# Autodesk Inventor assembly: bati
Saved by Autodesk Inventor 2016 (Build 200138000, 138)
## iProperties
Created: 2013-10
Part Number: bati
Material: Générique
Document SubType Name: Assembly
Designer: Bruno
Author: Bruno
Sending System: SolidWorks 2013
Last Author: christophe
Last Saved: 2014-02-15
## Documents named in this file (16)
- D:\Cours\Systèmes SI\Robot Haptique\Documentations_pedagogique\Modèle solidworks\Réel\bati.iam
- D:\Cours\Systèmes SI\Robot Haptique\Documentations_pedagogique\Modèle solidworks\Réel\MOTEUR.ipt
- D:\Cours\Systèmes SI\Robot Haptique\Documentations_pedagogique\Modèle solidworks\Réel\FIXATION MOTEUR.ipt
- D:\Cours\Systèmes SI\Robot Haptique\Documentations_pedagogique\Modèle solidworks\Réel\Vis à tôle tête cylindrique cruciforme H 2,9x13 - C.ipt
- D:\Cours\Systèmes SI\Robot Haptique\Documentations_pedagogique\Modèle solidworks\Réel\socle.ipt
- D:\Cours\Systèmes SI\Robot Haptique\Documentations_pedagogique\Modèle solidworks\Réel\vis CHC M4-30.ipt
- D:\Cours\Systèmes SI\Robot Haptique\Documentations_pedagogique\Modèle solidworks\Réel\Rondelle M4.ipt
- D:\Cours\Systèmes SI\Robot Haptique\Documentations_pedagogique\Modèle solidworks\Réel\CARTE HEXAGONALE.ipt
- D:\Cours\Systèmes SI\Robot Haptique\Documentations_pedagogique\Modèle solidworks\Réel\petite carte.ipt
- D:\Cours\Systèmes SI\Robot Haptique\Documentations_pedagogique\Modèle solidworks\Réel\Vis à tôle tête cylindrique cruciforme H 2,9x8 - C.ipt
- D:\Cours\Systèmes SI\Robot Haptique\Documentations_pedagogique\Modèle solidworks\Réel\plaque fixation.ipt
- D:\Cours\Systèmes SI\Robot Haptique\Documentations_pedagogique\Modèle solidworks\Réel\CARTER ARRIERE.ipt
- D:\Cours\Systèmes SI\Robot Haptique\Documentations_pedagogique\Modèle solidworks\Réel\carter transparant.iam
- D:\Cours\Systèmes SI\Robot Haptique\Documentations_pedagogique\Modèle solidworks\Réel\carter avant.iam
- D:\Cours\Systèmes SI\Robot Haptique\Documentations_pedagogique\Modèle solidworks\Réel\PLAQUE NOM.ipt
- D:\Cours\Systèmes SI\Robot Haptique\Documentations_pedagogique\Modèle solidworks\Réel\CACHE.ipt
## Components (51 placed, 15 different names)
1. MOTEUR:1
2. FIXATION MOTEUR:1
3. FIXATION MOTEUR:2
4. Vis à tôle tête cylindrique cruciforme H 2,9x13 - C:1
5. Vis à tôle tête cylindrique cruciforme H 2,9x13 - C:2
6. Vis à tôle tête cylindrique cruciforme H 2,9x13 - C:3
7. Vis à tôle tête cylindrique cruciforme H 2,9x13 - C:4
8. socle:1
9. vis CHC M4-30:1
10. vis CHC M4-30:2
11. Rondelle M4:1
12. Rondelle M4:2
13. CARTE HEXAGONALE:1
14. Vis à tôle tête cylindrique cruciforme H 2,9x13 - C:5
15. petite carte:1
16. Vis à tôle tête cylindrique cruciforme H 2,9x8 - C:1
17. Vis à tôle tête cylindrique cruciforme H 2,9x13 - C:7
18. Vis à tôle tête cylindrique cruciforme H 2,9x8 - C:2
19. Vis à tôle tête cylindrique cruciforme H 2,9x8 - C:3
20. petite carte:2
21. petite carte:3
22. Vis à tôle tête cylindrique cruciforme H 2,9x13 - C:8
23. Vis à tôle tête cylindrique cruciforme H 2,9x13 - C:9
24. Vis à tôle tête cylindrique cruciforme H 2,9x13 - C:10
25. Vis à tôle tête cylindrique cruciforme H 2,9x13 - C:11
26. Vis à tôle tête cylindrique cruciforme H 2,9x13 - C:12
27. Vis à tôle tête cylindrique cruciforme H 2,9x13 - C:13
28. Vis à tôle tête cylindrique cruciforme H 2,9x13 - C:14
29. Vis à tôle tête cylindrique cruciforme H 2,9x13 - C:15
30. MOTEUR:2
31. MOTEUR:3
32. FIXATION MOTEUR:3
33. FIXATION MOTEUR:4
34. Vis à tôle tête cylindrique cruciforme H 2,9x13 - C:16
35. Vis à tôle tête cylindrique cruciforme H 2,9x13 - C:17
36. plaque fixation:1
37. CARTER ARRIERE:1
38. carter transparant:5 [sub-assembly]
39. Vis à tôle tête cylindrique cruciforme H 2,9x13 - C:18
40. Vis à tôle tête cylindrique cruciforme H 2,9x13 - C:19
41. Vis à tôle tête cylindrique cruciforme H 2,9x13 - C:20
42. Vis à tôle tête cylindrique cruciforme H 2,9x13 - C:21
43. Vis à tôle tête cylindrique cruciforme H 2,9x13 - C:22
44. Vis à tôle tête cylindrique cruciforme H 2,9x13 - C:23
45. carter avant:1 [sub-assembly]
46. FIXATION MOTEUR:5
47. FIXATION MOTEUR:6
48. PLAQUE NOM:1
49. CACHE:1
50. CACHE:2
51. CACHE:3
